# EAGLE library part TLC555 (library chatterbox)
linCMOS Timer
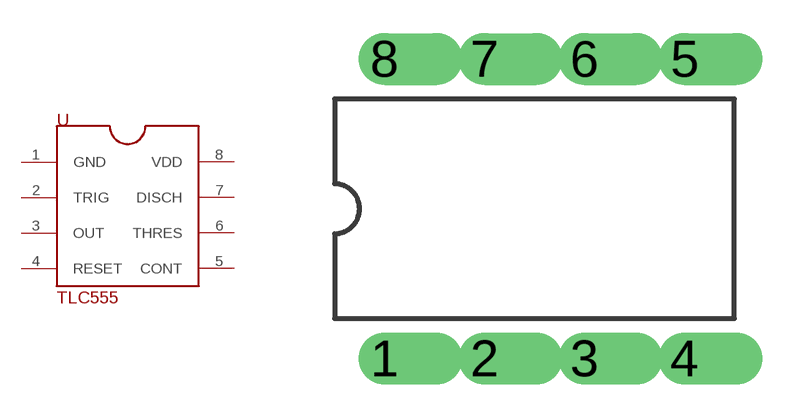
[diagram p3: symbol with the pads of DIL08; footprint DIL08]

Designator prefix -

## TLC555D  [DIL08]
1  GND  pwr
2  TRIG  pas
3  OUT  out
4  RESET  in
5  CONT  pas
6  THRES  pas
7  DISCH  pas
8  VDD  pwr

## Footprint DIL08 (pad centres in mm)
Dual In Line 8
drill 0.813 offset: 1 -3.81,-3.81; 2 -1.27,-3.81; 3 1.27,-3.81; 4 3.81,-3.81; 5 3.81,3.81; 6 1.27,3.81; 7 -1.27,3.81; 8 -3.81,3.81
